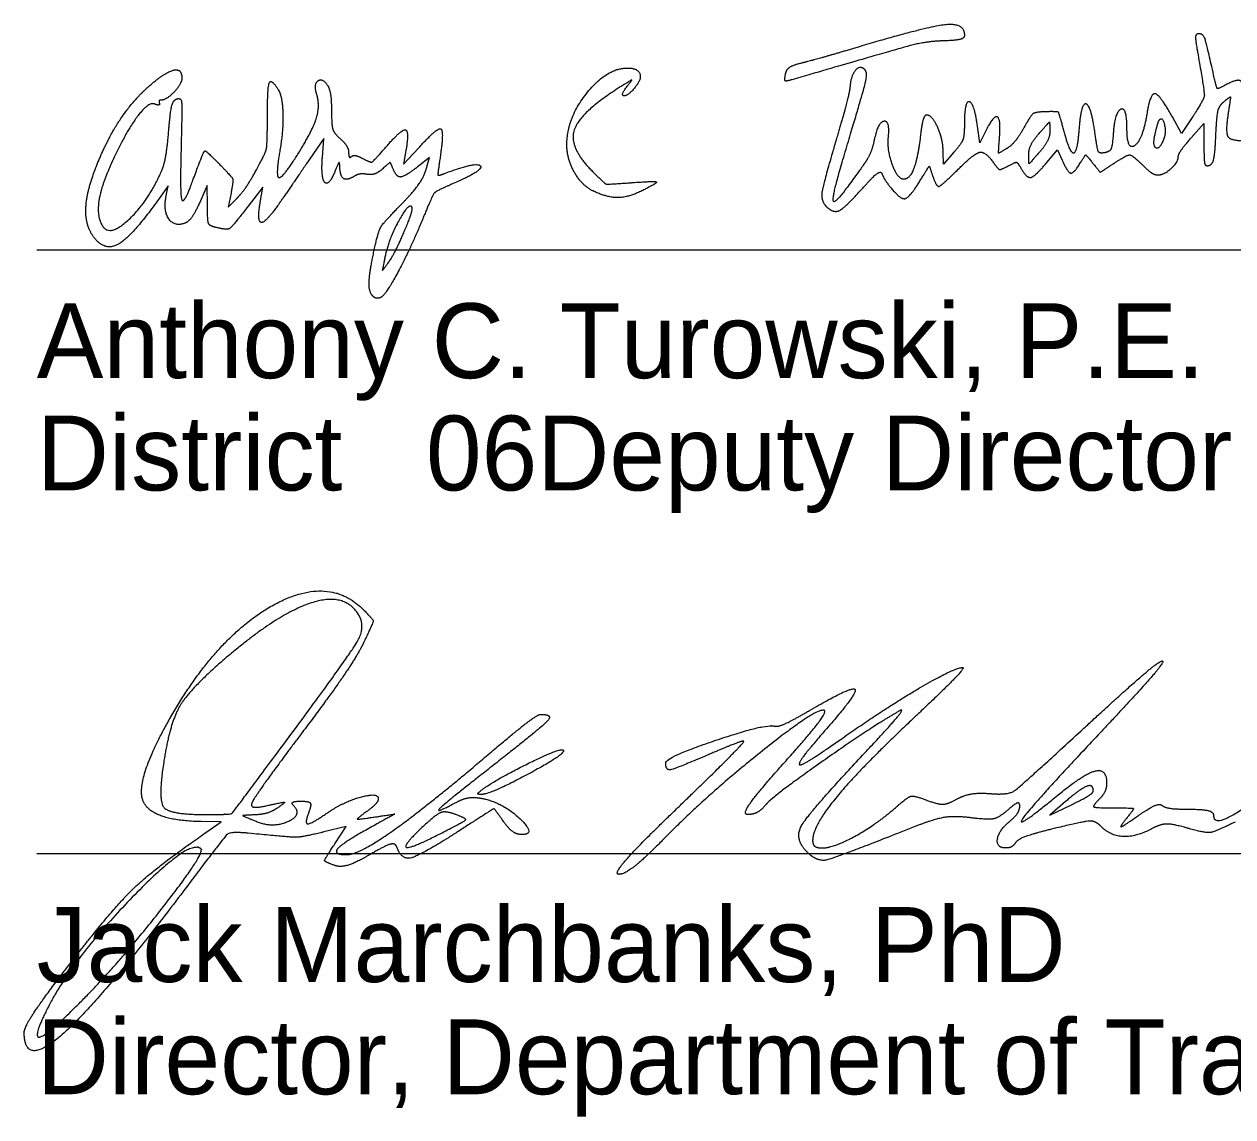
# Model space of a CAD drawing. Extents: x -7.1 to 34, y 0 to 22.
# Drawn here: x 24.504 to 26.766, y 3.013 to 5.057 of the extents above; entities that cross this region are included whole.
import ezdxf

# ---------------------------------------------------------------- set-up
doc = ezdxf.new("R2010")
doc.units = 0
doc.layers.add('SH_Data', color=7, linetype='Continuous')
doc.layers.add('SH_Text', color=7, linetype='Continuous')

msp = doc.modelspace()

# ---------------------------------------------------------------- linework, layer by layer
at = {"layer": 'SH_Data'}
for p, q in [((24.5279, 4.6347), (28.0279, 4.6347)), ((24.5279, 3.5053), (28.0279, 3.5053))]:
    msp.add_line(p, q, dxfattribs=at)
at = {"layer": 'SH_Text'}
for p, q in [((25.9287, 4.9631), (25.9287, 4.9631)), ((25.5689, 4.7448), (25.5689, 4.7448)), ((25.2156, 4.669), (25.2156, 4.669)), ((25.157, 4.5479), (25.157, 4.5479)), ((24.9902, 3.7103), (24.9902, 3.7103)), ((25.3555, 3.6204), (25.3555, 3.6204)), ((26.5045, 3.6225), (26.5045, 3.6225)), ((25.3107, 3.5788), (25.3107, 3.5788)), ((25.7273, 3.5914), (25.7273, 3.5914))]:
    msp.add_line(p, q, dxfattribs=at)
for points in [[(26.3033, 4.857), (26.2923, 4.8348), (26.2879, 4.8661)], [(26.6905, 4.8838), (26.6698, 4.8526), (26.6524, 4.8836)], [(26.6875, 4.844), (26.7115, 4.8713), (26.7115, 4.8304)], [(25.0623, 4.8074), (25.0648, 4.8428), (25.032, 4.7948)], [(25.2187, 4.8204), (25.2144, 4.7948), (25.2425, 4.8255)], [(26.2437, 4.8172), (26.224, 4.7948), (26.2237, 4.8172)], [(26.4178, 4.7982), (26.4375, 4.8216), (26.4463, 4.8022)], [(25.2556, 4.7831), (25.2625, 4.8071), (25.2419, 4.7909)], [(24.7697, 4.7323), (24.774, 4.7544), (24.757, 4.7306)], [(24.8473, 4.7177), (24.8471, 4.7548), (24.8322, 4.722)], [(24.946, 4.7234), (24.9507, 4.752), (24.9233, 4.7161)], [(24.8914, 4.741), (24.8859, 4.7148), (24.902, 4.7308)], [(26.4527, 3.6028), (26.4232, 3.5772), (26.4638, 3.5968)], [(24.8425, 3.5434), (24.8732, 3.5646), (24.8354, 3.5652)], [(25.0855, 3.5235), (25.1067, 3.5559), (25.0649, 3.5458)]]:
    msp.add_lwpolyline(points, dxfattribs=at)
for points in [[(26.0677, 5.0153), (26.1931, 5.0526), (26.2635, 5.06), (26.2635, 5.0358)], [(26.2253, 5.0256), (26.1933, 5.0247), (26.1405, 5.0111), (25.9407, 4.9528)], [(26.2635, 5.0358), (26.2635, 5.0305), (26.2477, 5.0263), (26.2253, 5.0256)], [(26.7022, 5.0388), (26.6963, 5.0388), (26.6954, 5.0276), (26.6995, 5.0048)], [(26.7309, 4.9566), (26.7165, 5.0204), (26.7101, 5.0388), (26.7022, 5.0388)], [(25.9595, 4.9846), (25.9749, 4.9883), (26.0236, 5.0021), (26.0677, 5.0153)], [(26.6995, 5.0048), (26.7128, 4.9299), (26.7117, 4.9159), (26.6905, 4.8838)], [(25.5197, 4.8324), (25.5201, 4.8815), (25.5945, 4.9748), (25.6332, 4.9748)], [(25.6332, 4.9748), (25.6521, 4.9748), (25.6602, 4.9541), (25.6474, 4.9387)], [(25.9287, 4.9631), (25.9304, 4.9722), (25.9422, 4.9803), (25.9595, 4.9846)], [(26.0773, 4.9716), (26.0685, 4.9804), (26.0512, 4.9613), (26.0495, 4.9411)], [(24.7437, 4.9457), (24.7705, 4.9683), (24.7995, 4.9736), (24.7995, 4.956)], [(24.7995, 4.956), (24.7995, 4.9454), (24.7707, 4.9148), (24.7606, 4.9148)], [(25.0516, 4.9265), (25.0458, 4.9447), (25.0625, 4.9571), (25.0723, 4.9418)], [(25.6325, 4.9406), (25.6421, 4.9527), (25.6405, 4.9526), (25.6195, 4.9393)], [(25.9407, 4.9528), (25.9295, 4.9495), (25.9266, 4.9521), (25.9287, 4.9631)], [(26.039, 4.813), (26.0736, 4.9284), (26.0827, 4.9662), (26.0773, 4.9716)], [(26.7525, 4.9433), (26.7378, 4.9354), (26.7353, 4.937), (26.7309, 4.9566)], [(26.7823, 4.8991), (26.7857, 4.9427), (26.7766, 4.9562), (26.7525, 4.9433)], [(24.6396, 4.7911), (24.6598, 4.8423), (24.7107, 4.918), (24.7437, 4.9457)], [(24.9595, 4.8823), (24.9595, 4.9382), (24.9665, 4.9558), (24.9801, 4.9338)], [(24.9801, 4.9338), (24.9876, 4.9217), (24.9892, 4.8573), (24.983, 4.8213)], [(25.0723, 4.9418), (25.0761, 4.9357), (25.0793, 4.9142), (25.0794, 4.894)], [(25.6195, 4.9393), (25.5442, 4.8918), (25.5228, 4.8262), (25.5678, 4.7812)], [(25.6474, 4.9387), (25.6335, 4.9219), (25.6192, 4.9238), (25.6325, 4.9406)], [(26.0495, 4.9411), (26.0487, 4.9309), (26.0371, 4.8858), (26.0237, 4.8409)], [(24.7485, 4.9075), (24.7359, 4.9123), (24.6881, 4.8441), (24.6629, 4.7855)], [(24.7574, 4.909), (24.7584, 4.9059), (24.7544, 4.9052), (24.7485, 4.9075)], [(24.7606, 4.9148), (24.7578, 4.9148), (24.7563, 4.9122), (24.7574, 4.909)], [(24.775, 4.8581), (24.7778, 4.8934), (24.7833, 4.9148), (24.79, 4.917)], [(24.79, 4.917), (24.7983, 4.9197), (24.7999, 4.9007), (24.798, 4.8236)], [(25.015, 4.8113), (25.0431, 4.8557), (25.0586, 4.9043), (25.0516, 4.9265)], [(26.2879, 4.8661), (26.2818, 4.9096), (26.2635, 4.9139), (26.2635, 4.8719)], [(26.5075, 4.8543), (26.5005, 4.9053), (26.4815, 4.9099), (26.4779, 4.8614)], [(26.6524, 4.8836), (26.629, 4.9255), (26.6111, 4.928), (26.605, 4.8904)], [(26.7338, 4.8487), (26.7355, 4.8854), (26.7401, 4.9046), (26.7492, 4.9121)], [(26.7492, 4.9121), (26.7609, 4.9217), (26.7616, 4.9197), (26.7571, 4.8913)], [(25.0794, 4.894), (25.0795, 4.8675), (25.084, 4.8532), (25.0955, 4.8428)], [(26.1924, 4.8868), (26.1887, 4.8868), (26.1837, 4.8695), (26.1812, 4.8484)], [(26.2237, 4.8172), (26.2235, 4.8416), (26.2031, 4.8868), (26.1924, 4.8868)], [(26.4155, 4.893), (26.3961, 4.8925), (26.3878, 4.8863), (26.3747, 4.8631)], [(26.4493, 4.8581), (26.4407, 4.8906), (26.4377, 4.8936), (26.4155, 4.893)], [(26.5675, 4.8628), (26.5675, 4.9022), (26.5449, 4.8934), (26.5419, 4.8528)], [(26.605, 4.8904), (26.5969, 4.8407), (26.5675, 4.819), (26.5675, 4.8628)], [(26.7571, 4.8913), (26.7513, 4.8552), (26.7608, 4.8388), (26.7876, 4.8388)], [(24.9388, 4.7843), (24.9559, 4.8153), (24.9595, 4.8323), (24.9595, 4.8823)], [(26.1212, 4.8451), (26.1245, 4.8769), (26.1015, 4.8733), (26.0949, 4.841)], [(26.2635, 4.8719), (26.2635, 4.849), (26.2578, 4.8331), (26.2437, 4.8172)], [(26.3291, 4.8436), (26.332, 4.8798), (26.3181, 4.887), (26.3033, 4.857)], [(26.3747, 4.8631), (26.3657, 4.847), (26.3512, 4.8294), (26.3425, 4.824)], [(26.4032, 4.8523), (26.4221, 4.8738), (26.423, 4.874), (26.4232, 4.8572)], [(26.4779, 4.8614), (26.4746, 4.8163), (26.461, 4.8147), (26.4493, 4.8581)], [(26.6205, 4.8528), (26.6234, 4.8649), (26.6269, 4.8762), (26.6284, 4.8779)], [(26.6284, 4.8779), (26.634, 4.8844), (26.641, 4.8542), (26.6366, 4.8428)], [(24.7618, 4.7828), (24.7666, 4.7938), (24.7725, 4.8277), (24.775, 4.8581)], [(25.0955, 4.8428), (25.1043, 4.8348), (25.1115, 4.8228), (25.1115, 4.8162)], [(25.1806, 4.8264), (25.2101, 4.8604), (25.225, 4.8581), (25.2187, 4.8204)], [(25.2425, 4.8255), (25.2773, 4.8637), (25.2902, 4.8583), (25.2828, 4.8088)], [(26.0237, 4.8409), (25.9997, 4.7599), (25.9946, 4.7263), (26.0048, 4.7161)], [(26.0949, 4.841), (26.092, 4.8268), (26.0839, 4.807), (26.0769, 4.797)], [(26.1498, 4.7668), (26.1386, 4.7668), (26.1187, 4.8212), (26.1212, 4.8451)], [(26.1812, 4.8484), (26.1762, 4.8063), (26.161, 4.7668), (26.1498, 4.7668)], [(26.3425, 4.824), (26.3277, 4.8148), (26.3269, 4.8161), (26.3291, 4.8436)], [(26.3837, 4.8123), (26.3836, 4.822), (26.3924, 4.84), (26.4032, 4.8523)], [(26.4232, 4.8572), (26.4234, 4.8475), (26.4146, 4.8295), (26.4037, 4.8172)], [(26.5263, 4.8164), (26.516, 4.8144), (26.5119, 4.8228), (26.5075, 4.8543)], [(26.5419, 4.8528), (26.5402, 4.8289), (26.5356, 4.8182), (26.5263, 4.8164)], [(26.6366, 4.8428), (26.6283, 4.8212), (26.6149, 4.8295), (26.6205, 4.8528)], [(26.6635, 4.8089), (26.6635, 4.8132), (26.6743, 4.8289), (26.6875, 4.844)], [(26.7215, 4.7927), (26.7278, 4.7948), (26.7324, 4.8155), (26.7338, 4.8487)], [(24.798, 4.8236), (24.7966, 4.7703), (24.7979, 4.7267), (24.8008, 4.7267)], [(24.8201, 4.7648), (24.8401, 4.8191), (24.8441, 4.8212), (24.8721, 4.7926)], [(24.983, 4.8213), (24.9743, 4.7718), (24.9874, 4.7677), (25.015, 4.8113)], [(25.1115, 4.8162), (25.1115, 4.8095), (25.1138, 4.8064), (25.1165, 4.8091)], [(25.1382, 4.8053), (25.1526, 4.7976), (25.1582, 4.8004), (25.1806, 4.8264)], [(25.5689, 4.7448), (25.5476, 4.755), (25.5194, 4.8053), (25.5197, 4.8324)], [(26.2518, 4.7854), (26.2818, 4.8154), (26.3025, 4.8192), (26.318, 4.7975)], [(26.4037, 4.8172), (26.3849, 4.7957), (26.384, 4.7955), (26.3837, 4.8123)], [(26.7115, 4.8304), (26.7115, 4.8012), (26.7144, 4.7904), (26.7215, 4.7927)], [(25.032, 4.7948), (25.0139, 4.7684), (24.9911, 4.7352), (24.9813, 4.7211)], [(25.087, 4.7841), (25.0747, 4.7534), (25.0596, 4.7677), (25.0623, 4.8074)], [(25.095, 4.7892), (25.0946, 4.7987), (25.0922, 4.7972), (25.087, 4.7841)], [(25.1165, 4.8091), (25.1193, 4.8119), (25.1291, 4.8102), (25.1382, 4.8053)], [(25.1942, 4.7871), (25.19, 4.7981), (25.188, 4.7981), (25.1752, 4.7865)], [(25.2828, 4.8088), (25.2779, 4.7762), (25.2788, 4.7728), (25.2911, 4.7775)], [(25.2911, 4.7775), (25.3506, 4.8004), (25.365, 4.7834), (25.3071, 4.7586)], [(26.0769, 4.797), (26.0249, 4.7223), (26.0132, 4.7272), (26.039, 4.813)], [(26.318, 4.7975), (26.3265, 4.7854), (26.3315, 4.7843), (26.3451, 4.7916)], [(26.3451, 4.7916), (26.3585, 4.7988), (26.3633, 4.798), (26.3691, 4.7877)], [(26.3691, 4.7877), (26.3798, 4.7685), (26.3957, 4.7719), (26.4178, 4.7982)], [(26.4463, 4.8022), (26.4569, 4.7788), (26.4681, 4.7775), (26.4808, 4.7979)], [(26.4808, 4.7979), (26.49, 4.8127), (26.4907, 4.8126), (26.5039, 4.7963)], [(26.5039, 4.7963), (26.5173, 4.7797), (26.5176, 4.7797), (26.5405, 4.7949)], [(26.5405, 4.7949), (26.5671, 4.8127), (26.5784, 4.8118), (26.5999, 4.7903)], [(26.6249, 4.7748), (26.6366, 4.7748), (26.6635, 4.7986), (26.6635, 4.8089)], [(24.6342, 4.6591), (24.6185, 4.6806), (24.6211, 4.7441), (24.6396, 4.7911)], [(24.6629, 4.7855), (24.6464, 4.747), (24.6408, 4.6961), (24.6511, 4.6794)], [(24.6511, 4.6794), (24.6644, 4.6579), (24.7369, 4.7256), (24.7618, 4.7828)], [(24.8721, 4.7926), (24.8933, 4.771), (24.8961, 4.7634), (24.8914, 4.741)], [(24.902, 4.7308), (24.9109, 4.7396), (24.9275, 4.7636), (24.9388, 4.7843)], [(25.1215, 4.7721), (25.1084, 4.7639), (25.0956, 4.7722), (25.095, 4.7892)], [(25.1462, 4.7759), (25.1381, 4.7773), (25.127, 4.7755), (25.1215, 4.7721)], [(25.1752, 4.7865), (25.1673, 4.7794), (25.1542, 4.7746), (25.1462, 4.7759)], [(25.2419, 4.7909), (25.2173, 4.7716), (25.2007, 4.7703), (25.1942, 4.7871)], [(25.2086, 4.7184), (25.2307, 4.7408), (25.2518, 4.7699), (25.2556, 4.7831)], [(25.5678, 4.7812), (25.5906, 4.7585), (25.5952, 4.7571), (25.6398, 4.7603)], [(26.0719, 4.7488), (26.0918, 4.7711), (26.1072, 4.7827), (26.1092, 4.7769)], [(26.1092, 4.7769), (26.1112, 4.7714), (26.1191, 4.7591), (26.1269, 4.7495)], [(26.1826, 4.7673), (26.197, 4.7908), (26.1982, 4.7913), (26.2032, 4.7756)], [(26.2032, 4.7756), (26.2106, 4.7524), (26.2208, 4.7544), (26.2518, 4.7854)], [(26.5999, 4.7903), (26.6085, 4.7818), (26.6197, 4.7748), (26.6249, 4.7748)], [(24.8008, 4.7267), (24.8038, 4.7267), (24.8125, 4.7439), (24.8201, 4.7648)], [(25.3071, 4.7586), (25.2757, 4.7451), (25.2684, 4.7373), (25.2535, 4.7009)], [(25.6398, 4.7603), (25.666, 4.7622), (25.6875, 4.7627), (25.6875, 4.7615)], [(25.6875, 4.7615), (25.6875, 4.7602), (25.6769, 4.7537), (25.6639, 4.747)], [(26.0048, 4.7161), (26.0182, 4.7027), (26.0408, 4.7137), (26.0719, 4.7488)], [(26.1269, 4.7495), (26.1444, 4.7279), (26.1621, 4.7335), (26.1826, 4.7673)], [(24.757, 4.7306), (24.7073, 4.6608), (24.6552, 4.6304), (24.6342, 4.6591)], [(24.8052, 4.6845), (24.7863, 4.6773), (24.7648, 4.7064), (24.7697, 4.7323)], [(25.6639, 4.747), (25.6366, 4.7329), (25.5956, 4.7319), (25.5689, 4.7448)], [(24.8322, 4.722), (24.8241, 4.7039), (24.8119, 4.6871), (24.8052, 4.6845)], [(24.8615, 4.677), (24.8507, 4.6798), (24.8474, 4.6892), (24.8473, 4.7177)], [(24.9233, 4.7161), (24.894, 4.6778), (24.8837, 4.6712), (24.8615, 4.677)], [(24.9813, 4.7211), (24.9565, 4.6853), (24.94, 4.6864), (24.946, 4.7234)], [(25.16, 4.6378), (25.1667, 4.669), (25.1773, 4.6866), (25.2086, 4.7184)], [(25.2295, 4.7154), (25.2229, 4.722), (25.1859, 4.6533), (25.1798, 4.6228)], [(25.2156, 4.669), (25.2255, 4.6922), (25.2318, 4.7131), (25.2295, 4.7154)], [(25.2535, 4.7009), (25.2283, 4.6392), (25.1799, 4.5482), (25.1705, 4.5451)], [(25.1858, 4.6108), (25.1922, 4.6196), (25.2056, 4.6458), (25.2156, 4.669)], [(25.157, 4.5479), (25.149, 4.5559), (25.1502, 4.5921), (25.16, 4.6378)], [(25.1798, 4.6228), (25.1745, 4.5968), (25.175, 4.5959), (25.1858, 4.6108)], [(25.1705, 4.5451), (25.1661, 4.5436), (25.16, 4.5449), (25.157, 4.5479)], [(24.7789, 3.7611), (24.8651, 3.9114), (25.0732, 4.0275), (25.1389, 3.9618)], [(25.1299, 3.9526), (25.104, 3.9946), (24.9779, 3.9535), (24.8825, 3.8719)], [(25.1389, 3.9618), (25.1577, 3.943), (25.1577, 3.938), (25.1394, 3.8996)], [(24.9902, 3.7103), (25.1115, 3.8738), (25.144, 3.93), (25.1299, 3.9526)], [(25.1394, 3.8996), (25.1284, 3.8766), (25.0767, 3.801), (25.0245, 3.7317)], [(24.8825, 3.8719), (24.8159, 3.8148), (24.7771, 3.7507), (24.766, 3.6794)], [(26.0326, 3.7195), (26.1131, 3.7761), (26.2445, 3.8534), (26.2602, 3.8534)], [(26.2602, 3.8534), (26.265, 3.8534), (26.2237, 3.8108), (26.1684, 3.7587)], [(26.4869, 3.7399), (26.5619, 3.809), (26.6279, 3.8657), (26.6336, 3.8657)], [(26.6336, 3.8657), (26.6394, 3.8658), (26.5873, 3.8057), (26.518, 3.7321)], [(25.9736, 3.773), (26.0524, 3.8192), (26.0646, 3.806), (26.0054, 3.7387)], [(24.8354, 3.5652), (24.7375, 3.5669), (24.7141, 3.6481), (24.7789, 3.7611)], [(25.369, 3.6876), (25.4194, 3.7304), (25.4649, 3.7656), (25.4701, 3.7657)], [(25.4701, 3.7657), (25.495, 3.7662), (25.4716, 3.7406), (25.3857, 3.6734)], [(26.0017, 3.7728), (25.9921, 3.7824), (25.7824, 3.6155), (25.7045, 3.5362)], [(26.142, 3.7723), (26.0929, 3.7446), (25.9046, 3.6123), (25.8914, 3.5964)], [(25.908, 3.7438), (25.9136, 3.742), (25.9431, 3.7551), (25.9736, 3.773)], [(25.9239, 3.6724), (25.9702, 3.7242), (26.0052, 3.7693), (26.0017, 3.7728)], [(26.1684, 3.7587), (26.0687, 3.665), (25.9795, 3.5568), (25.9795, 3.5298)], [(26.0768, 3.6934), (26.123, 3.7427), (26.1523, 3.7782), (26.142, 3.7723)], [(25.0245, 3.7317), (24.9722, 3.6623), (24.9295, 3.6016), (24.9295, 3.5969)], [(25.7047, 3.6753), (25.7049, 3.6858), (25.8923, 3.749), (25.908, 3.7438)], [(26.0054, 3.7387), (25.9774, 3.7068), (25.9545, 3.6772), (25.9545, 3.6727)], [(26.3119, 3.6176), (26.3453, 3.6147), (26.3688, 3.6312), (26.4869, 3.7399)], [(26.518, 3.7321), (26.3885, 3.5945), (26.3564, 3.5472), (26.4386, 3.615)], [(24.844, 3.5784), (24.8907, 3.5784), (24.8953, 3.5825), (24.9902, 3.7103)], [(25.7273, 3.5914), (25.7983, 3.6599), (25.8537, 3.7159), (25.8502, 3.7159)], [(25.8502, 3.7159), (25.8468, 3.7159), (25.8178, 3.7046), (25.7857, 3.6909)], [(25.9545, 3.6727), (25.9545, 3.6683), (25.9896, 3.6893), (26.0326, 3.7195)], [(25.1076, 3.5034), (25.1307, 3.5034), (25.2567, 3.5922), (25.369, 3.6876)], [(25.3555, 3.6204), (25.3759, 3.6383), (25.5079, 3.7041), (25.5131, 3.6989)], [(25.5131, 3.6989), (25.5193, 3.6928), (25.3767, 3.6159), (25.359, 3.6159)], [(25.7857, 3.6909), (25.7231, 3.6641), (25.7044, 3.6604), (25.7047, 3.6753)], [(25.9697, 3.5078), (25.9445, 3.533), (25.9734, 3.5831), (26.0768, 3.6934)], [(24.766, 3.6794), (24.7545, 3.6061), (24.776, 3.5784), (24.844, 3.5784)], [(25.3857, 3.6734), (25.2925, 3.6004), (25.271, 3.5788), (25.315, 3.6023)], [(25.8581, 3.5784), (25.8478, 3.5784), (25.8767, 3.6197), (25.9239, 3.6724)], [(26.7295, 3.5769), (26.7295, 3.5541), (26.8248, 3.6155), (26.8951, 3.6837)], [(26.4386, 3.615), (26.487, 3.6549), (26.5295, 3.6652), (26.5295, 3.6371)], [(25.359, 3.6159), (25.3542, 3.6159), (25.3526, 3.6179), (25.3555, 3.6204)], [(26.2489, 3.6071), (26.2623, 3.6146), (26.2906, 3.6194), (26.3119, 3.6176)], [(26.5045, 3.6225), (26.5045, 3.6359), (26.4804, 3.6268), (26.4527, 3.6028)], [(26.4638, 3.5968), (26.4862, 3.6077), (26.5045, 3.6192), (26.5045, 3.6225)], [(26.5295, 3.6371), (26.5295, 3.6282), (26.5227, 3.6141), (26.5145, 3.6059)], [(24.9295, 3.5969), (24.9295, 3.5921), (24.9449, 3.5918), (24.9638, 3.5962)], [(24.9399, 3.5651), (24.9698, 3.5531), (25.026, 3.5777), (25.0086, 3.5951)], [(24.9638, 3.5962), (24.9894, 3.6021), (24.9934, 3.6009), (24.9795, 3.5915)], [(25.0086, 3.5951), (25.004, 3.5997), (25.0103, 3.6034), (25.0225, 3.6034)], [(25.0225, 3.6034), (25.037, 3.6034), (25.0422, 3.597), (25.0375, 3.5846)], [(25.0736, 3.5828), (25.1025, 3.6026), (25.167, 3.6201), (25.167, 3.6081)], [(25.167, 3.6081), (25.167, 3.6036), (25.1572, 3.5928), (25.1453, 3.5841)], [(25.315, 3.6023), (25.3276, 3.6091), (25.3515, 3.6112), (25.3681, 3.607)], [(25.3681, 3.607), (25.4042, 3.5978), (25.4625, 3.5409), (25.4358, 3.5409)], [(25.8914, 3.5964), (25.8831, 3.5865), (25.8682, 3.5784), (25.8581, 3.5784)], [(26.137, 3.5934), (26.1573, 3.6114), (26.1701, 3.6141), (26.1939, 3.605)], [(26.1939, 3.605), (26.2141, 3.5974), (26.2329, 3.5981), (26.2489, 3.6071)], [(26.367, 3.5944), (26.367, 3.6015), (26.3568, 3.5981), (26.3444, 3.5868)], [(26.5145, 3.6059), (26.5028, 3.5942), (26.5087, 3.5909), (26.541, 3.5909)], [(26.5871, 3.5754), (26.6085, 3.5904), (26.6293, 3.5994), (26.6332, 3.5955)], [(26.6332, 3.5955), (26.6371, 3.5916), (26.6604, 3.5884), (26.6849, 3.5884)], [(24.9357, 3.5778), (24.9133, 3.5769), (24.9138, 3.5756), (24.9399, 3.5651)], [(24.9795, 3.5915), (24.9692, 3.5845), (24.9495, 3.5783), (24.9357, 3.5778)], [(25.0375, 3.5846), (25.0285, 3.5614), (25.0414, 3.5607), (25.0736, 3.5828)], [(25.1453, 3.5841), (25.1264, 3.5703), (25.1284, 3.569), (25.161, 3.5739)], [(25.161, 3.5739), (25.1977, 3.5794), (25.1976, 3.5792), (25.1522, 3.5541)], [(25.3107, 3.5788), (25.2935, 3.5851), (25.277, 3.58), (25.2576, 3.5623)], [(25.2826, 3.5425), (25.329, 3.5662), (25.3325, 3.5708), (25.3107, 3.5788)], [(25.4011, 3.5656), (25.3843, 3.5896), (25.3822, 3.5892), (25.3165, 3.5468)], [(25.617, 3.4666), (25.6067, 3.4668), (25.6563, 3.523), (25.7273, 3.5914)], [(25.9975, 3.5159), (26.0192, 3.5159), (26.1006, 3.5611), (26.137, 3.5934)], [(26.2749, 3.5724), (26.2457, 3.5762), (26.2058, 3.5697), (26.1693, 3.5553)], [(26.3444, 3.5868), (26.3287, 3.5727), (26.3075, 3.5682), (26.2749, 3.5724)], [(26.3482, 3.5659), (26.3585, 3.5744), (26.367, 3.5873), (26.367, 3.5944)], [(26.541, 3.5909), (26.5785, 3.5909), (26.5809, 3.5888), (26.5654, 3.5695)], [(26.5654, 3.5695), (26.5533, 3.5545), (26.5598, 3.5563), (26.5871, 3.5754)], [(26.6849, 3.5884), (26.7094, 3.5884), (26.7295, 3.5832), (26.7295, 3.5769)], [(25.1522, 3.5541), (25.1011, 3.5259), (25.0814, 3.5034), (25.1076, 3.5034)], [(25.2576, 3.5623), (25.2133, 3.5218), (25.2246, 3.5129), (25.2826, 3.5425)], [(25.4358, 3.5409), (25.4262, 3.5409), (25.4106, 3.552), (25.4011, 3.5656)], [(26.1693, 3.5553), (26.0233, 3.4976), (25.9882, 3.4893), (25.9697, 3.5078)], [(26.3412, 3.5159), (26.3229, 3.5159), (26.3274, 3.5486), (26.3482, 3.5659)], [(26.4355, 3.5533), (26.3972, 3.5441), (26.3629, 3.532), (26.3594, 3.5263)], [(26.5199, 3.5555), (26.5088, 3.5666), (26.4887, 3.5661), (26.4355, 3.5533)], [(26.6162, 3.553), (26.5854, 3.5365), (26.5376, 3.5378), (26.5199, 3.5555)], [(26.6807, 3.553), (26.6538, 3.5608), (26.6307, 3.5607), (26.6162, 3.553)], [(26.7698, 3.5644), (26.7324, 3.5459), (26.7138, 3.5435), (26.6807, 3.553)], [(24.5916, 3.3012), (24.6692, 3.4016), (24.7493, 3.4789), (24.8425, 3.5434)], [(24.9237, 3.5435), (24.8903, 3.5468), (24.8786, 3.5363), (24.8019, 3.4346)], [(25.0649, 3.5458), (25.0246, 3.536), (25.0023, 3.5357), (24.9237, 3.5435)], [(25.3165, 3.5468), (25.2476, 3.5024), (25.2101, 3.4927), (25.202, 3.5171)], [(25.7045, 3.5362), (25.6667, 3.4977), (25.6273, 3.4664), (25.617, 3.4666)], [(25.9795, 3.5298), (25.9795, 3.5222), (25.9876, 3.5159), (25.9975, 3.5159)], [(24.8354, 3.5141), (24.8145, 3.535), (24.596, 3.3094), (24.5497, 3.219)], [(24.6198, 3.2378), (24.6874, 3.3068), (24.8431, 3.5064), (24.8354, 3.5141)], [(25.0843, 3.4835), (25.0661, 3.4904), (25.0662, 3.4941), (25.0855, 3.5235)], [(25.202, 3.5171), (25.1991, 3.5256), (25.1799, 3.5204), (25.1508, 3.5033)], [(26.3594, 3.5263), (26.3559, 3.5206), (26.3477, 3.5159), (26.3412, 3.5159)], [(25.1508, 3.5033), (25.1252, 3.4882), (25.0953, 3.4792), (25.0843, 3.4835)], [(24.8019, 3.4346), (24.6496, 3.2326), (24.5045, 3.1039), (24.5045, 3.1709)], [(24.5045, 3.1709), (24.5045, 3.1805), (24.5437, 3.2392), (24.5916, 3.3012)], [(24.5497, 3.219), (24.5184, 3.1581), (24.55, 3.1665), (24.6198, 3.2378)]]:
    msp.add_open_spline(points, degree=2, dxfattribs=at)

# ---------------------------------------------------------------- texts
for s, p in [('Anthony C. Turowski, P.E.', (24.5279, 4.3947)), ('District       Deputy Director', (24.5279, 4.1847)), ('              06', (24.5279, 4.1847)), ('Jack Marchbanks, PhD', (24.5279, 3.2653)), ('Director, Department of Transportation', (24.5279, 3.0553))]:
    msp.add_text(s, height=0.14, dxfattribs=at).set_placement(p)

doc.saveas('drawing.dxf')
